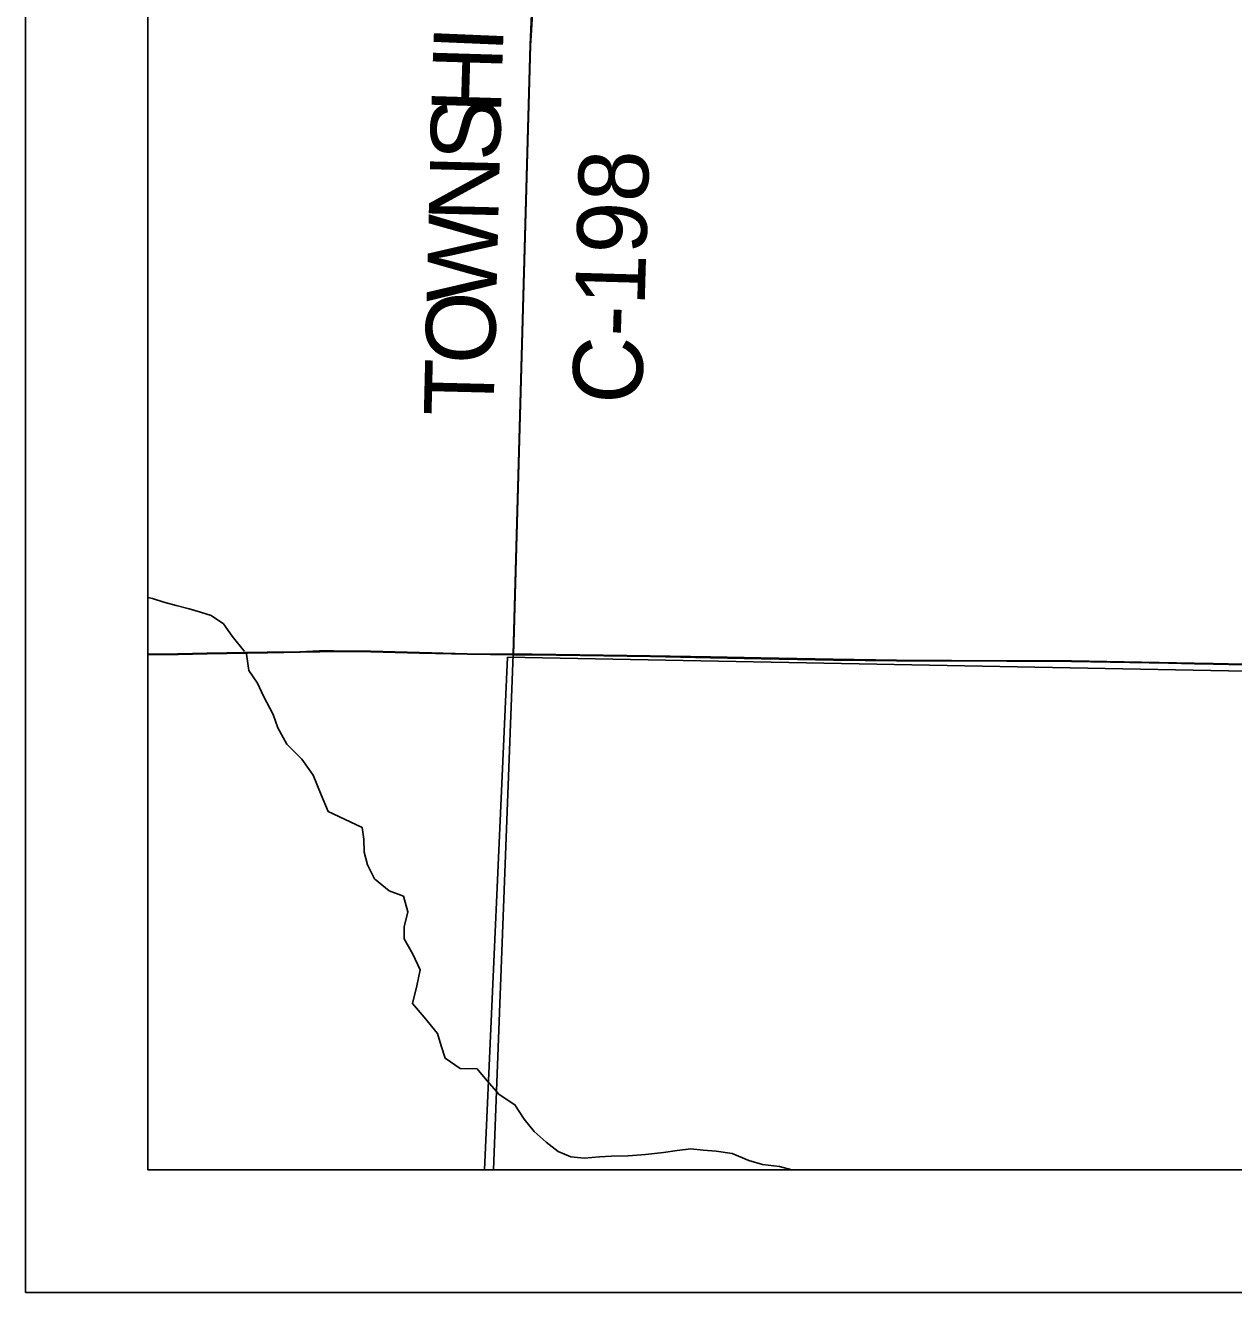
# Model space of a CAD drawing. Extents: x 0 to 34, y 0 to 22.
# Drawn here: x 2 to 2.985, y 14 to 15.033 of the extents above; entities that cross this region are included whole.
import ezdxf

# ---------------------------------------------------------------- set-up
doc = ezdxf.new("R2010")
doc.units = 0
for name, color, linetype in [('GM_X_County_Road', 7, 'Continuous'), ('GM_X_County_Road_Text', 7, 'Continuous'), ('GM_X_Minor_River', 7, 'Continuous'), ('GM_X_Township', 7, 'Continuous'), ('GM_X_Township_Road', 7, 'Continuous'), ('GM_X_Unincorporated', 7, 'Continuous'), ('SH_Cut_Line', 7, 'Continuous'), ('SH_Data', 7, 'Continuous')]:
    doc.layers.add(name, color=color, linetype=linetype)

msp = doc.modelspace()

# ---------------------------------------------------------------- linework, layer by layer
at = {"layer": 'GM_X_County_Road'}
for p, q in [((2.4124, 15.0248), (2.4438, 15.5292)), ((2.8532, 14.5145), (2.9323, 14.5131)), ((2.9323, 14.5131), (2.9534, 14.5127))]:
    msp.add_line(p, q, dxfattribs=at)
for points in [[(2.398, 14.52), (2.4119, 15.0167), (2.4124, 15.0248)], [(2.1, 14.52), (2.1247, 14.5203), (2.1483, 14.5207), (2.1974, 14.5215), (2.2241, 14.522), (2.2401, 14.5225), (2.2514, 14.5228), (2.2817, 14.5223), (2.3215, 14.5213), (2.3606, 14.5204), (2.398, 14.52)], [(2.398, 14.52), (2.4134, 14.5199), (2.4526, 14.5193), (2.5097, 14.5185), (2.5588, 14.5176), (2.6, 14.5168), (2.6589, 14.5157), (2.7105, 14.5151), (2.8005, 14.5147), (2.8532, 14.5145)], [(2.9534, 14.5127), (2.9688, 14.5124), (2.9938, 14.5118), (3.0049, 14.5117)]]:
    msp.add_lwpolyline(points, dxfattribs=at)
at = {"layer": 'GM_X_Minor_River'}
for points in [[(2.1, 14.5667), (2.1038, 14.5658), (2.1129, 14.563), (2.1231, 14.5603), (2.1337, 14.5575), (2.1428, 14.5548), (2.1515, 14.552), (2.1616, 14.5451), (2.1687, 14.5351), (2.1787, 14.5227)], [(2.18, 14.5225), (2.1823, 14.5072), (2.1894, 14.4969), (2.1943, 14.4863), (2.2021, 14.4714), (2.2058, 14.4604), (2.2133, 14.4471), (2.2254, 14.4349), (2.2347, 14.4219), (2.2411, 14.4059), (2.247, 14.3922), (2.2603, 14.3861), (2.2746, 14.3792), (2.2761, 14.3697), (2.2764, 14.3591), (2.2789, 14.3488), (2.2846, 14.3374), (2.2966, 14.3275), (2.3083, 14.3232), (2.312, 14.3103), (2.3089, 14.2982), (2.3088, 14.2883), (2.316, 14.2758), (2.3219, 14.2632), (2.3192, 14.25), (2.3157, 14.2356), (2.3251, 14.2245), (2.336, 14.2112), (2.339, 14.2013), (2.3423, 14.191), (2.3547, 14.1826), (2.3684, 14.1825), (2.3763, 14.173), (2.3864, 14.1616), (2.3992, 14.1531), (2.4067, 14.1413), (2.415, 14.1314), (2.4248, 14.1226), (2.4346, 14.115), (2.4448, 14.1108), (2.4557, 14.1095), (2.4682, 14.1106), (2.4781, 14.1113), (2.4917, 14.1116), (2.5057, 14.1127), (2.5205, 14.1141), (2.5315, 14.1159), (2.5428, 14.1173), (2.5527, 14.1162), (2.5633, 14.1153), (2.5765, 14.1133), (2.5901, 14.1076), (2.6011, 14.1045), (2.6151, 14.1029), (2.6251, 14.1)]]:
    msp.add_lwpolyline(points, dxfattribs=at)
at = {"layer": 'GM_X_Township'}
msp.add_lwpolyline([(2.9935, 14.5123), (2.9686, 14.513), (2.9531, 14.5133), (2.853, 14.515), (2.8002, 14.5152), (2.7103, 14.5157), (2.6587, 14.5163), (2.5998, 14.5174), (2.5586, 14.5182), (2.5095, 14.5191), (2.4523, 14.5199), (2.4132, 14.5204), (2.3978, 14.5206), (2.4116, 15.0173), (2.4334, 15.5145)], dxfattribs=at)
at = {"layer": 'GM_X_Township_Road'}
for points in [[(2.1, 20.3739), (2.1, 14.5206), (2.1244, 14.5209), (2.148, 14.5212), (2.1972, 14.522), (2.2239, 14.5225), (2.2399, 14.5231), (2.2512, 14.5233), (2.2815, 14.5229), (2.3213, 14.5218), (2.3604, 14.5209), (2.3978, 14.5206), (2.4116, 15.0173), (2.4334, 15.5145)], [(2.9935, 14.5123), (2.9686, 14.513), (2.9531, 14.5133), (2.853, 14.515), (2.8002, 14.5152), (2.7103, 14.5157), (2.6587, 14.5163), (2.5998, 14.5174), (2.5586, 14.5182), (2.5095, 14.5191), (2.4523, 14.5199), (2.4132, 14.5204), (2.3978, 14.5206), (2.3817, 14.1), (8.4746, 14.1)]]:
    msp.add_lwpolyline(points, dxfattribs=at)
msp.add_lwpolyline([(2.1, 14.5206), (2.1, 14.1), (2.3817, 14.1), (2.3978, 14.5206), (2.3604, 14.5209), (2.3213, 14.5218), (2.2815, 14.5229), (2.2512, 14.5233), (2.2399, 14.5231), (2.2239, 14.5225), (2.1972, 14.522), (2.148, 14.5212), (2.1244, 14.5209)], close=True, dxfattribs=at)
at = {"layer": 'GM_X_Unincorporated'}
msp.add_lwpolyline([(2.3744, 14.1), (3.3529, 14.1), (3.3539, 14.4998), (2.3933, 14.518)], close=True, dxfattribs=at)
at = {"layer": 'SH_Cut_Line'}
for points in [[(2.1, 20.9), (2.1, 14.5206), (2.1244, 14.5209), (2.148, 14.5212), (2.1972, 14.522), (2.2239, 14.5225), (2.2399, 14.5231), (2.2512, 14.5233), (2.2815, 14.5229), (2.3213, 14.5218), (2.3604, 14.5209), (2.3978, 14.5206), (2.4132, 14.5204), (2.4523, 14.5199), (2.5095, 14.5191), (2.5586, 14.5182), (2.5998, 14.5174), (2.6587, 14.5163), (2.7103, 14.5157), (2.8002, 14.5152), (2.853, 14.515), (2.9531, 14.5133), (2.9686, 14.513), (2.9935, 14.5123)], [(2.9935, 14.5123), (2.9686, 14.513), (2.9531, 14.5133), (2.853, 14.515), (2.8002, 14.5152), (2.7103, 14.5157), (2.6587, 14.5163), (2.5998, 14.5174), (2.5586, 14.5182), (2.5095, 14.5191), (2.4523, 14.5199), (2.4132, 14.5204), (2.3978, 14.5206), (2.3604, 14.5209), (2.3213, 14.5218), (2.2815, 14.5229), (2.2512, 14.5233), (2.2399, 14.5231), (2.2239, 14.5225), (2.1972, 14.522), (2.148, 14.5212), (2.1244, 14.5209), (2.1, 14.5206), (2.1, 14.1), (8.9, 14.1)]]:
    msp.add_lwpolyline(points, dxfattribs=at)
at = {"layer": 'SH_Data'}
for p, q in [((2, 21), (2, 14)), ((2.1, 20.9), (2.1, 14.1)), ((2.1, 14.1), (8.9, 14.1)), ((2.1, 14.1), (2.1, 14.1)), ((2, 14), (9, 14))]:
    msp.add_line(p, q, dxfattribs=at)

# ---------------------------------------------------------------- texts
at = {"layer": 'GM_X_County_Road_Text'}
for s, height, rotation, p in [('I', 0.0568, 87.5716, (2.3893, 15.0103)), ('H', 0.0568, 88.2803, (2.3878, 14.9605)), ('S', 0.0568, 88.5833, (2.3869, 14.9222)), ('N', 0.0568, 88.5828, (2.3856, 14.8722)), ('C-198', 0.05682, 88.3475, (2.5027, 14.7239)), ('W', 0.0568, 88.5833, (2.384, 14.8064)), ('O', 0.0568, 88.5828, (2.3828, 14.7564)), ('T', 0.0568, 88.5856, (2.3817, 14.714))]:
    msp.add_text(s, height=height, rotation=rotation, dxfattribs=at).set_placement(p)

doc.saveas('drawing.dxf')
